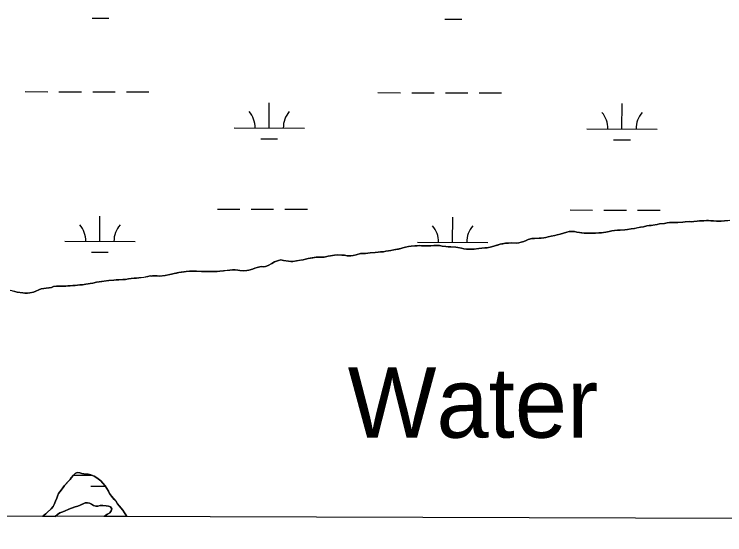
# Model space of a CAD drawing. Extents: x 3161514 to 3199414, y 831166 to 856601.
# Drawn here: x 3187612 to 3188623, y 836546 to 837286 of the extents above; entities that cross this region are included whole.
import ezdxf

# ---------------------------------------------------------------- set-up
doc = ezdxf.new("R2010")
doc.units = 0
for name, color, linetype in [('V-GRID-FRAM', 7, 'Continuous'), ('V-RIVR-IDEN', 7, 'Continuous'), ('V-TOPO-SHOR', 7, 'Continuous'), ('V-WETL-SWMP', 7, 'Continuous')]:
    doc.layers.add(name, color=color, linetype=linetype)

msp = doc.modelspace()

# ---------------------------------------------------------------- linework, layer by layer
at = {"layer": 'V-GRID-FRAM'}
msp.add_lwpolyline([(3165761, 854820), (3197144.3, 854733.3), (3197102, 836546.1), (3165702.9, 836632.9), (3165761, 854820)], dxfattribs=at)
at = {"layer": 'V-TOPO-SHOR'}
for points in [[(3188388.8, 836973.7), (3188393.1, 836975.2), (3188397.9, 836976.6), (3188401.2, 836977.3), (3188405.3, 836977.3), (3188409.1, 836977.2), (3188412.1, 836976.4), (3188415.9, 836976.1), (3188419, 836975.6), (3188422.5, 836975), (3188425.6, 836975), (3188428.8, 836975), (3188432.4, 836974.9), (3188435.7, 836974.9), (3188438.7, 836975.1), (3188443.8, 836975.3), (3188447.4, 836975.7), (3188450.4, 836975.9), (3188453.5, 836976.4), (3188458.3, 836977.4), (3188461.9, 836978.3), (3188465.7, 836978.8), (3188470, 836979.5), (3188473.8, 836979.5), (3188477.1, 836979.7), (3188480.6, 836979.9), (3188484.2, 836980.3), (3188489.8, 836981.3), (3188494.1, 836981.7), (3188497.7, 836982.4), (3188502.8, 836983.4), (3188507.3, 836984.1), (3188511.7, 836985.3), (3188515, 836985.8), (3188518, 836986), (3188523.3, 836986.9), (3188526.4, 836987.4), (3188529.7, 836988.1), (3188533.8, 836988.6), (3188537.1, 836989), (3188540.9, 836989.8), (3188544.2, 836990), (3188548.2, 836990.2), (3188552.5, 836990.4), (3188556.1, 836990.3), (3188562.9, 836990.5), (3188566.5, 836991), (3188572.1, 836991.4), (3188575.4, 836991.3), (3188578.7, 836991.6), (3188583.3, 836992), (3188586.6, 836992.5), (3188589.9, 836992.7), (3188593.2, 836992.6), (3188596.7, 836993.1), (3188599.8, 836993.1), (3188603, 836992.8), (3188606.6, 836992.5), (3188610.9, 836991.9), (3188614.2, 836991.9), (3188617.5, 836992.1), (3188622.6, 836992.5), (3188626.9, 836993)], [(3187990.9, 836936.9), (3187995, 836936.1), (3187998.7, 836935.5), (3188001.8, 836935), (3188005.3, 836934.7), (3188008.4, 836934.7), (3188013.2, 836935.6), (3188018.8, 836936.6), (3188022.9, 836937.3), (3188026.2, 836938.2), (3188030, 836939.2), (3188033.5, 836939.7), (3188036.8, 836940.1), (3188041.4, 836940.8), (3188046, 836941), (3188049, 836941), (3188052.8, 836940.9), (3188058.7, 836942.1), (3188061.7, 836942.6), (3188067.3, 836943.8), (3188072.1, 836944.2), (3188077.7, 836943.9), (3188081.5, 836943.6), (3188085.6, 836942.8), (3188090.9, 836942.7), (3188093.9, 836943.2), (3188098.5, 836944.4), (3188104.6, 836945.9), (3188107.9, 836946.3), (3188111.7, 836946.3), (3188115, 836946.7), (3188118.3, 836947.2), (3188122.4, 836947.4), (3188125.4, 836947.6), (3188129.8, 836948.1), (3188133.1, 836948.3), (3188137.1, 836948.7), (3188140.7, 836949.5), (3188144.2, 836949.9), (3188147.5, 836950.6), (3188151.9, 836951.1), (3188154.9, 836951.8), (3188158.5, 836952.5), (3188161.8, 836953.2), (3188164.8, 836954.2), (3188168.4, 836955.2), (3188172.7, 836956.1), (3188176.5, 836956.4), (3188181.6, 836957.1), (3188185.2, 836957), (3188188.5, 836957.5), (3188191.5, 836957.2), (3188195.3, 836956.9), (3188199.4, 836957.1), (3188204.4, 836957), (3188209, 836957.5), (3188213.3, 836957.4), (3188216.9, 836957.4), (3188220.9, 836956.6), (3188225.7, 836956), (3188229, 836955.7), (3188232.8, 836955.4), (3188239.9, 836955), (3188243.2, 836954.5), (3188248, 836953.7), (3188251.3, 836952.9), (3188255.1, 836952.3), (3188261.2, 836952.2), (3188266, 836952.4), (3188269.1, 836952.9), (3188272.9, 836953.4), (3188276.9, 836953.6), (3188281.5, 836954), (3188284.8, 836954.2), (3188291.1, 836955.4), (3188295.5, 836956.9), (3188299.6, 836958.1), (3188303.4, 836959.3), (3188307.2, 836960), (3188310.7, 836960.7), (3188315.1, 836960.9), (3188319.4, 836961.1), (3188322.7, 836961.1), (3188326, 836961), (3188329.8, 836961.5), (3188333.1, 836962.2), (3188336.9, 836963.4), (3188340, 836964.7), (3188343, 836966.2), (3188348.4, 836967.6), (3188352.2, 836967.6), (3188355.2, 836967.8), (3188358.5, 836968), (3188361.6, 836968), (3188365.1, 836968.2), (3188368.4, 836968.9), (3188371.7, 836969.8), (3188375.8, 836970.8), (3188381.1, 836971.8), (3188384.2, 836972.5), (3188388.8, 836973.7)], [(3187609.4, 836892.8), (3187612.5, 836892), (3187616, 836891.2), (3187620.1, 836890.7), (3187624.1, 836890.1), (3187627.1, 836889.8), (3187630.7, 836889.8), (3187634, 836890), (3187639.1, 836891.2), (3187642.7, 836892.6), (3187646.7, 836894.6), (3187650, 836895.9), (3187653.9, 836896.3), (3187657.4, 836896.8), (3187661.7, 836897.5), (3187665, 836897.9), (3187667.8, 836899.2), (3187671.7, 836899.6), (3187676.5, 836899.6), (3187680.5, 836899.5), (3187685.1, 836899.5), (3187688.1, 836899.9), (3187691.4, 836900.1), (3187695.2, 836900.6), (3187698.6, 836900.8), (3187701.6, 836901), (3187705.1, 836901.5), (3187708.7, 836901.4), (3187713.8, 836902.4), (3187716.8, 836903.1), (3187719.9, 836903.3), (3187723.4, 836903.8), (3187729, 836905.2), (3187732.6, 836906), (3187736.2, 836906.4), (3187742.8, 836907.4), (3187746.6, 836907.8), (3187753.7, 836908.2), (3187757, 836908.7), (3187760.8, 836908.9), (3187766.4, 836909.3), (3187769.9, 836909.3), (3187774.2, 836910), (3187778.3, 836910.5), (3187782.6, 836911.2), (3187785.7, 836911.1), (3187789.2, 836911.3), (3187792.3, 836911.8), (3187796.1, 836912.3), (3187801.7, 836913.2), (3187805, 836914.2), (3187807, 836914.1), (3187808.3, 836914.4), (3187811.8, 836914.3), (3187815.4, 836914.3), (3187818.4, 836914), (3187822.5, 836914.5), (3187826.5, 836914.9), (3187830.6, 836915.6), (3187835.7, 836916.6), (3187839.3, 836917.5), (3187842.6, 836918.3), (3187845.9, 836919), (3187853.5, 836920.1), (3187856.5, 836920.6), (3187861.1, 836921.1), (3187864.2, 836920.8), (3187867.5, 836921), (3187871.3, 836921.2), (3187874.6, 836920.9), (3187878.1, 836920.6), (3187881.6, 836920.5), (3187887.2, 836920.5), (3187890.8, 836920.4), (3187896.1, 836920.4), (3187900.4, 836920.6), (3187904.2, 836920.8), (3187909.6, 836921.5), (3187914.9, 836922.2), (3187918.4, 836922.4), (3187922.5, 836923.1), (3187926.1, 836923), (3187929.9, 836922.2), (3187932.9, 836921.9), (3187938.2, 836921.6), (3187942.8, 836921.8), (3187945.8, 836922.5), (3187950.7, 836924), (3187954.2, 836925.2), (3187957.3, 836926.4), (3187963.1, 836927.4), (3187966.2, 836927.3), (3187969.2, 836927.8), (3187973, 836929), (3187978.2, 836932), (3187982.2, 836934.2), (3187987.6, 836936.2), (3187990.9, 836936.9)], [(3187772, 836571.9), (3187770.7, 836574.5), (3187768.7, 836577.3), (3187766.5, 836581.2), (3187761, 836587.3), (3187758.8, 836590.1), (3187756.8, 836593.2), (3187754, 836596.5), (3187750.3, 836601.2), (3187747.5, 836605), (3187745.8, 836608.1), (3187741.1, 836615.5), (3187737.8, 836619.6), (3187734.8, 836622.7), (3187729.3, 836627.3), (3187725.5, 836629.4), (3187721, 836631.5), (3187717.2, 836632.3), (3187713.9, 836632.1), (3187710.9, 836632.6), (3187707.8, 836633.1), (3187705.1, 836634.4), (3187701.2, 836634.5), (3187698.4, 836633.3), (3187696.1, 836631), (3187693, 836627.2), (3187691.2, 836624.7), (3187687.6, 836620.7), (3187683.5, 836616.2), (3187681.2, 836613.2), (3187678.4, 836609.7), (3187675, 836604.7), (3187673.2, 836601.1), (3187672.4, 836598.1), (3187670.3, 836593.8), (3187668.7, 836589.3), (3187667.2, 836586.5), (3187664.3, 836583.2), (3187658.7, 836578), (3187656.6, 836575.7), (3187653, 836573), (3187652.1, 836572.2)], [(3187669.9, 836572.2), (3187670, 836572.3), (3187673.4, 836575), (3187676.9, 836577.5), (3187680.8, 836578.7), (3187684.3, 836580.2), (3187688.7, 836582.2), (3187691.7, 836583.6), (3187694.8, 836584.6), (3187698.6, 836585.8), (3187702.4, 836586.8), (3187705.5, 836588.3), (3187708.8, 836589.8), (3187712.6, 836591.5), (3187715.9, 836591.5), (3187719, 836590.9), (3187721.7, 836589.6), (3187724.7, 836587.8), (3187727.8, 836587), (3187730.8, 836587), (3187733.9, 836587.7), (3187737.7, 836587.6), (3187742.5, 836587.1), (3187746, 836587), (3187748.8, 836585.7), (3187750.6, 836583.2), (3187749.8, 836580.1), (3187747.7, 836577.4), (3187744.4, 836575.4), (3187740.5, 836572.9), (3187739.7, 836572)]]:
    msp.add_lwpolyline(points, dxfattribs=at)
at = {"layer": 'V-WETL-SWMP'}
for p, q in [((3187722.5, 837280.7), (3187746.5, 837280.6)), ((3188224.5, 837279.3), (3188248.5, 837279.2)), ((3187627.4, 837176.3), (3187659.4, 837176.2)), ((3187675.4, 837176.2), (3187707.4, 837176.1)), ((3187723.4, 837176.1), (3187755.4, 837176)), ((3187771.4, 837175.9), (3187803.4, 837175.8)), ((3188129.3, 837174.9), (3188161.3, 837174.8)), ((3188177.3, 837174.8), (3188209.3, 837174.7)), ((3188225.3, 837174.7), (3188257.3, 837174.6)), ((3188273.3, 837174.5), (3188305.3, 837174.4)), ((3187974.6, 837124.6), (3187974.7, 837160.6)), ((3188476.5, 837123.2), (3188476.6, 837159.2)), ((3187924.6, 837124.8), (3188024.6, 837124.5)), ((3188426.5, 837123.4), (3188526.5, 837123.1)), ((3187962.5, 837109.2), (3187986.5, 837109.2)), ((3188464.5, 837107.8), (3188488.5, 837107.8)), ((3187900.9, 837009.4), (3187932.9, 837009.3)), ((3187948.9, 837009.3), (3187980.9, 837009.2)), ((3187996.9, 837009.1), (3188028.9, 837009)), ((3187733.7, 836963.4), (3187733.8, 836999.4)), ((3188402.8, 837008), (3188434.8, 837007.9)), ((3188450.8, 837007.9), (3188482.8, 837007.8)), ((3188498.8, 837007.7), (3188530.8, 837007.6)), ((3188235.6, 836962), (3188235.7, 836998)), ((3188529.7, 836988.1), (3188526.4, 836987.4)), ((3188537.1, 836989), (3188529.7, 836988.1)), ((3188540.9, 836989.8), (3188537.1, 836989)), ((3188544.2, 836990), (3188540.9, 836989.8)), ((3188548.2, 836990.2), (3188544.2, 836990)), ((3188552.5, 836990.4), (3188548.2, 836990.2)), ((3188556.1, 836990.3), (3188552.5, 836990.4)), ((3188562.9, 836990.5), (3188556.1, 836990.3)), ((3188566.5, 836991), (3188562.9, 836990.5)), ((3188572.1, 836991.4), (3188566.5, 836991)), ((3188575.4, 836991.3), (3188572.1, 836991.4)), ((3188578.7, 836991.6), (3188575.4, 836991.3)), ((3188583.3, 836992), (3188578.7, 836991.6)), ((3188586.6, 836992.5), (3188583.3, 836992)), ((3188589.9, 836992.7), (3188586.6, 836992.5)), ((3188593.2, 836992.6), (3188589.9, 836992.7)), ((3188596.7, 836993.1), (3188593.2, 836992.6)), ((3188599.7, 836993.1), (3188596.7, 836993.1)), ((3188606.6, 836992.5), (3188599.7, 836993.1)), ((3188610.9, 836991.9), (3188606.6, 836992.5)), ((3188614.2, 836991.9), (3188610.9, 836991.9)), ((3188630.2, 836993.2), (3188614.2, 836991.9)), ((3188461.9, 836978.3), (3188458.3, 836977.4)), ((3188465.7, 836978.8), (3188461.9, 836978.3)), ((3188470, 836979.5), (3188465.7, 836978.8)), ((3188473.8, 836979.5), (3188470, 836979.5)), ((3188480.6, 836979.9), (3188473.8, 836979.5)), ((3188484.2, 836980.3), (3188480.6, 836979.9)), ((3188489.8, 836981.3), (3188484.2, 836980.3)), ((3188494.1, 836981.7), (3188489.8, 836981.3)), ((3188502.8, 836983.4), (3188494.1, 836981.7)), ((3188507.3, 836984.1), (3188502.8, 836983.4)), ((3188511.7, 836985.3), (3188507.3, 836984.1)), ((3188515, 836985.8), (3188511.7, 836985.3)), ((3188518, 836986), (3188515, 836985.8)), ((3188526.4, 836987.4), (3188518, 836986)), ((3188358.5, 836968), (3188352.2, 836967.6)), ((3188361.6, 836967.9), (3188358.5, 836968)), ((3188365.1, 836968.2), (3188361.6, 836967.9)), ((3188368.4, 836968.9), (3188365.1, 836968.2)), ((3188371.7, 836969.8), (3188368.4, 836968.9)), ((3188375.8, 836970.8), (3188371.7, 836969.8)), ((3188381.1, 836971.8), (3188375.8, 836970.8)), ((3188384.2, 836972.5), (3188381.1, 836971.8)), ((3188388.8, 836973.7), (3188384.2, 836972.5)), ((3188393.1, 836975.2), (3188388.8, 836973.7)), ((3188397.9, 836976.6), (3188393.1, 836975.2)), ((3188401.2, 836977.3), (3188397.9, 836976.6)), ((3188409.1, 836977.2), (3188401.2, 836977.3)), ((3188412.1, 836976.4), (3188409.1, 836977.2)), ((3188415.9, 836976.1), (3188412.1, 836976.4)), ((3188422.5, 836975), (3188415.9, 836976.1)), ((3188435.7, 836974.9), (3188422.5, 836975)), ((3188438.7, 836975.1), (3188435.7, 836974.9)), ((3188443.8, 836975.3), (3188438.7, 836975.1)), ((3188447.4, 836975.7), (3188443.8, 836975.3)), ((3188450.4, 836975.9), (3188447.4, 836975.7)), ((3188453.5, 836976.4), (3188450.4, 836975.9)), ((3188458.3, 836977.4), (3188453.5, 836976.4)), ((3187683.7, 836963.6), (3187783.7, 836963.3)), ((3188185.6, 836962.2), (3188285.6, 836961.9)), ((3188303.4, 836959.3), (3188295.5, 836956.9)), ((3188310.7, 836960.7), (3188303.4, 836959.3)), ((3188319.4, 836961.1), (3188310.7, 836960.7)), ((3188326, 836961), (3188319.4, 836961.1)), ((3188329.8, 836961.5), (3188326, 836961)), ((3188333.1, 836962.2), (3188329.8, 836961.5)), ((3188336.9, 836963.4), (3188333.1, 836962.2)), ((3188340, 836964.7), (3188336.9, 836963.4)), ((3188343, 836966.2), (3188340, 836964.7)), ((3188348.4, 836967.6), (3188343, 836966.2)), ((3188352.2, 836967.6), (3188348.4, 836967.6)), ((3187721.6, 836948), (3187745.6, 836948)), ((3188125.4, 836947.6), (3188118.3, 836947.2)), ((3188129.8, 836948.1), (3188125.4, 836947.6)), ((3188133.1, 836948.3), (3188129.8, 836948.1)), ((3188137.1, 836948.7), (3188133.1, 836948.3)), ((3188140.7, 836949.5), (3188137.1, 836948.7)), ((3188144.2, 836949.9), (3188140.7, 836949.5)), ((3188147.5, 836950.6), (3188144.2, 836949.9)), ((3188151.9, 836951.1), (3188147.5, 836950.6)), ((3188161.8, 836953.2), (3188151.9, 836951.1)), ((3188164.8, 836954.2), (3188161.8, 836953.2)), ((3188168.4, 836955.2), (3188164.8, 836954.2)), ((3188172.7, 836956.1), (3188168.4, 836955.2)), ((3188176.5, 836956.4), (3188172.7, 836956.1)), ((3188181.6, 836957), (3188176.5, 836956.4)), ((3188185.2, 836957), (3188181.6, 836957)), ((3188188.5, 836957.5), (3188185.2, 836957)), ((3188195.3, 836956.9), (3188188.5, 836957.5)), ((3188199.4, 836957.1), (3188195.3, 836956.9)), ((3188204.4, 836957), (3188199.4, 836957.1)), ((3188209, 836957.5), (3188204.4, 836957)), ((3188216.9, 836957.4), (3188209, 836957.5)), ((3188220.9, 836956.5), (3188216.9, 836957.4)), ((3188225.7, 836956), (3188220.9, 836956.5)), ((3188232.8, 836955.4), (3188225.7, 836956)), ((3188239.9, 836955), (3188232.8, 836955.4)), ((3188248, 836953.7), (3188239.9, 836955)), ((3188251.3, 836952.9), (3188248, 836953.7)), ((3188255.1, 836952.3), (3188251.3, 836952.9)), ((3188261.2, 836952.2), (3188255.1, 836952.3)), ((3188266, 836952.4), (3188261.2, 836952.2)), ((3188272.9, 836953.4), (3188266, 836952.4)), ((3188276.9, 836953.6), (3188272.9, 836953.4)), ((3188281.5, 836954), (3188276.9, 836953.6)), ((3188284.8, 836954.2), (3188281.5, 836954)), ((3188291.1, 836955.4), (3188284.8, 836954.2)), ((3188295.5, 836956.9), (3188291.1, 836955.4)), ((3188026.2, 836938.2), (3188022.9, 836937.3)), ((3188030, 836939.2), (3188026.2, 836938.2)), ((3188041.4, 836940.8), (3188030, 836939.2)), ((3188046, 836941), (3188041.4, 836940.8)), ((3188052.8, 836940.9), (3188046, 836941)), ((3188058.7, 836942.1), (3188052.8, 836940.9)), ((3188061.7, 836942.6), (3188058.7, 836942.1)), ((3188067.3, 836943.8), (3188061.7, 836942.6)), ((3188072.1, 836944.2), (3188067.3, 836943.8)), ((3188081.5, 836943.6), (3188072.1, 836944.2)), ((3188085.6, 836942.8), (3188081.5, 836943.6)), ((3188090.9, 836942.7), (3188085.6, 836942.8)), ((3188093.9, 836943.2), (3188090.9, 836942.7)), ((3188098.5, 836944.4), (3188093.9, 836943.2)), ((3188104.6, 836945.9), (3188098.5, 836944.4)), ((3188107.9, 836946.3), (3188104.6, 836945.9)), ((3188111.7, 836946.3), (3188107.9, 836946.3)), ((3188118.3, 836947.2), (3188111.7, 836946.3)), ((3187969.2, 836927.8), (3187966.2, 836927.3)), ((3187973, 836929), (3187969.2, 836927.8)), ((3187978.2, 836932), (3187973, 836929)), ((3187982.2, 836934.2), (3187978.2, 836932)), ((3187987.6, 836936.2), (3187982.2, 836934.2)), ((3187990.9, 836936.9), (3187987.6, 836936.2)), ((3187994.9, 836936.1), (3187990.9, 836936.9)), ((3188001.8, 836935), (3187994.9, 836936.1)), ((3188005.3, 836934.7), (3188001.8, 836935)), ((3188008.4, 836934.7), (3188005.3, 836934.7)), ((3188013.2, 836935.6), (3188008.4, 836934.7)), ((3188022.9, 836937.3), (3188013.2, 836935.6)), ((3187839.3, 836917.5), (3187835.7, 836916.6)), ((3187845.9, 836919), (3187839.3, 836917.5)), ((3187856.5, 836920.6), (3187845.9, 836919)), ((3187861.1, 836921.1), (3187856.5, 836920.6)), ((3187864.1, 836920.8), (3187861.1, 836921.1)), ((3187871.3, 836921.2), (3187864.1, 836920.8)), ((3187878.1, 836920.6), (3187871.3, 836921.2)), ((3187896.1, 836920.4), (3187878.1, 836920.6)), ((3187904.2, 836920.8), (3187896.1, 836920.4)), ((3187914.9, 836922.1), (3187904.2, 836920.8)), ((3187918.4, 836922.4), (3187914.9, 836922.1)), ((3187922.5, 836923.1), (3187918.4, 836922.4)), ((3187926.1, 836923), (3187922.5, 836923.1)), ((3187929.9, 836922.2), (3187926.1, 836923)), ((3187932.9, 836921.9), (3187929.9, 836922.2)), ((3187938.2, 836921.6), (3187932.9, 836921.9)), ((3187942.8, 836921.8), (3187938.2, 836921.6)), ((3187945.8, 836922.5), (3187942.8, 836921.8)), ((3187950.7, 836924), (3187945.8, 836922.5)), ((3187954.2, 836925.2), (3187950.7, 836924)), ((3187957.3, 836926.4), (3187954.2, 836925.2)), ((3187963.1, 836927.4), (3187957.3, 836926.4)), ((3187966.2, 836927.3), (3187963.1, 836927.4)), ((3187746.6, 836907.8), (3187732.6, 836906)), ((3187753.7, 836908.2), (3187746.6, 836907.8)), ((3187757, 836908.7), (3187753.7, 836908.2)), ((3187766.4, 836909.3), (3187757, 836908.7)), ((3187769.9, 836909.3), (3187766.4, 836909.3)), ((3187774.2, 836910), (3187769.9, 836909.3)), ((3187778.3, 836910.4), (3187774.2, 836910)), ((3187782.6, 836911.2), (3187778.3, 836910.4)), ((3187785.7, 836911.1), (3187782.6, 836911.2)), ((3187789.2, 836911.3), (3187785.7, 836911.1)), ((3187796.1, 836912.2), (3187789.2, 836911.3)), ((3187801.7, 836913.2), (3187796.1, 836912.2)), ((3187805, 836914.2), (3187801.7, 836913.2)), ((3187807, 836914.1), (3187805, 836914.2)), ((3187808.3, 836914.4), (3187807, 836914.1)), ((3187815.4, 836914.3), (3187808.3, 836914.4)), ((3187818.4, 836914), (3187815.4, 836914.3)), ((3187826.5, 836914.9), (3187818.4, 836914)), ((3187835.7, 836916.6), (3187826.5, 836914.9)), ((3187665, 836897.9), (3187657.4, 836896.8)), ((3187667.8, 836899.2), (3187665, 836897.9)), ((3187671.7, 836899.6), (3187667.8, 836899.2)), ((3187685.1, 836899.5), (3187671.7, 836899.6)), ((3187688.1, 836899.9), (3187685.1, 836899.5)), ((3187691.4, 836900.1), (3187688.1, 836899.9)), ((3187695.2, 836900.6), (3187691.4, 836900.1)), ((3187701.6, 836901), (3187695.2, 836900.6)), ((3187705.1, 836901.5), (3187701.6, 836901)), ((3187708.7, 836901.4), (3187705.1, 836901.5)), ((3187713.8, 836902.4), (3187708.7, 836901.4)), ((3187716.8, 836903.1), (3187713.8, 836902.4)), ((3187719.9, 836903.3), (3187716.8, 836903.1)), ((3187723.4, 836903.8), (3187719.9, 836903.3)), ((3187729, 836905.2), (3187723.4, 836903.8)), ((3187732.6, 836906), (3187729, 836905.2)), ((3187612.5, 836892), (3187605.9, 836893.6)), ((3187616, 836891.2), (3187612.5, 836892)), ((3187624.1, 836890.1), (3187616, 836891.2)), ((3187627.1, 836889.8), (3187624.1, 836890.1)), ((3187630.7, 836889.8), (3187627.1, 836889.8)), ((3187634, 836890), (3187630.7, 836889.8)), ((3187639.1, 836891.2), (3187634, 836890)), ((3187642.7, 836892.6), (3187639.1, 836891.2)), ((3187646.7, 836894.6), (3187642.7, 836892.6)), ((3187650, 836895.8), (3187646.7, 836894.6)), ((3187657.4, 836896.8), (3187650, 836895.8)), ((3187698.4, 836633.3), (3187701.2, 836634.5)), ((3187701.2, 836634.5), (3187705, 836634.4)), ((3187705, 836634.4), (3187707.8, 836633.1)), ((3187683.5, 836616.2), (3187691.2, 836624.7)), ((3187691.2, 836624.7), (3187693, 836627.2)), ((3187693, 836627.2), (3187696.1, 836631)), ((3187696, 836630.8), (3187722.5, 836630.8)), ((3187696.1, 836631), (3187698.4, 836633.3)), ((3187707.8, 836633.1), (3187713.9, 836632.1)), ((3187713.9, 836632.1), (3187717.2, 836632.3)), ((3187717.2, 836632.3), (3187721, 836631.5)), ((3187721, 836631.5), (3187725.5, 836629.4)), ((3187725.5, 836629.4), (3187729.3, 836627.3)), ((3187729.3, 836627.3), (3187734.8, 836622.7)), ((3187678.4, 836609.7), (3187683.5, 836616.2)), ((3187720.7, 836615.3), (3187741.2, 836615.3)), ((3187734.8, 836622.7), (3187737.8, 836619.6)), ((3187737.8, 836619.6), (3187741.1, 836615.5)), ((3187741.1, 836615.5), (3187745.8, 836608.1)), ((3187673.2, 836601.1), (3187675, 836604.7)), ((3187675, 836604.7), (3187678.4, 836609.7)), ((3187745.8, 836608.1), (3187747.5, 836605)), ((3187747.5, 836605), (3187750.3, 836601.2)), ((3187668.7, 836589.3), (3187670.3, 836593.8)), ((3187670.3, 836593.8), (3187672.4, 836598.1)), ((3187672.4, 836598.1), (3187673.2, 836601.1)), ((3187750.3, 836601.2), (3187756.8, 836593.2)), ((3187664.3, 836583.2), (3187667.2, 836586.5)), ((3187667.2, 836586.5), (3187668.7, 836589.3)), ((3187691.7, 836583.6), (3187684.3, 836580.2)), ((3187698.6, 836585.8), (3187691.7, 836583.6)), ((3187702.4, 836586.8), (3187698.6, 836585.8)), ((3187705.5, 836588.3), (3187702.4, 836586.8)), ((3187712.6, 836591.5), (3187705.5, 836588.3)), ((3187715.9, 836591.5), (3187712.6, 836591.5)), ((3187719, 836590.9), (3187715.9, 836591.5)), ((3187721.7, 836589.6), (3187719, 836590.9)), ((3187724.7, 836587.8), (3187721.7, 836589.6)), ((3187727.8, 836587), (3187724.7, 836587.8)), ((3187730.8, 836587), (3187727.8, 836587)), ((3187733.9, 836587.7), (3187730.8, 836587)), ((3187737.7, 836587.6), (3187733.9, 836587.7)), ((3187742.5, 836587.1), (3187737.7, 836587.6)), ((3187746, 836587), (3187742.5, 836587.1)), ((3187748.8, 836585.7), (3187746, 836587)), ((3187750.6, 836583.1), (3187748.8, 836585.7)), ((3187756.8, 836593.2), (3187758.8, 836590.1)), ((3187758.8, 836590.1), (3187761, 836587.3)), ((3187761, 836587.3), (3187766.5, 836581.2)), ((3187653, 836573), (3187656.6, 836575.7)), ((3187656.6, 836575.7), (3187658.7, 836578)), ((3187658.7, 836578), (3187664.3, 836583.2)), ((3187673.4, 836575), (3187670, 836572.3)), ((3187676.9, 836577.5), (3187673.4, 836575)), ((3187680.8, 836578.7), (3187676.9, 836577.5)), ((3187684.3, 836580.2), (3187680.8, 836578.7)), ((3187740.5, 836572.9), (3187744.4, 836575.4)), ((3187744.4, 836575.4), (3187747.7, 836577.4)), ((3187747.7, 836577.4), (3187749.8, 836580.1)), ((3187749.8, 836580.1), (3187750.6, 836583.1)), ((3187766.5, 836581.2), (3187768.7, 836577.3)), ((3187768.7, 836577.3), (3187770.7, 836574.5)), ((3187770.7, 836574.5), (3187772, 836571.9)), ((3187652.1, 836572.2), (3187653, 836573)), ((3187669.9, 836572.2), (3187652.1, 836572.2)), ((3187670, 836572.3), (3187669.9, 836572.2)), ((3187739.7, 836572), (3187740.5, 836572.9)), ((3187772, 836571.9), (3187739.7, 836572))]:
    msp.add_line(p, q, dxfattribs=at)
for centre, start, end in [((3187919.3, 837125.2), 359.0699, 40.6135), ((3188029.8, 837124.9), 139.0699, 180.6135), ((3188421.3, 837123.9), 359.0699, 40.6135), ((3188531.7, 837123.6), 139.0699, 180.6135), ((3187678.4, 836964), 359.0699, 40.6135), ((3187788.9, 836963.7), 139.0699, 180.6135), ((3188180.3, 836962.7), 359.0699, 40.6135), ((3188290.8, 836962.4), 139.0699, 180.6135), ((3187677.5, 836631.4), 359.0699, 1.4399)]:
    msp.add_arc(centre, 35.2, start, end, dxfattribs=at)

# ---------------------------------------------------------------- texts
at = {"layer": 'V-RIVR-IDEN'}
msp.add_text('Water', height=100, dxfattribs=at).set_placement((3188086.3, 836684.2))

doc.saveas('drawing.dxf')
